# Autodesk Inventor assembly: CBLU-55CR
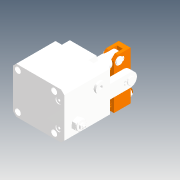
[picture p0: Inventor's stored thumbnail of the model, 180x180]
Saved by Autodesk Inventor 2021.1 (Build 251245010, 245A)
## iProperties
Created: 2019-05
Part Number: CBLU-55CR
Description: STEP AP214
Document SubType Name: Assembly
Designer: user
Title: CBLU-55CR.STEP
Revision Number: ÈÎºÎ
Sending System: SolidWorks 2016
Preprocessor: SwSTEP 2.0
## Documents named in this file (15)
- D:\Vault_2016\Projekty\Clamptek\Hydraulic\CBLU\CBLU-55\Inventor\CBLU-55CR\CBLU-55CR.iam
- D:\Vault_2016\Projekty\Clamptek\Hydraulic\CBLU\CBLU-55\Inventor\CBLU-55CR\CBLU-55CR±¾Ìå_2_1.ipt
- D:\Vault_2016\Projekty\Clamptek\Hydraulic\CBLU\CBLU-55\Inventor\CBLU-55CR\changxiao.ipt
- D:\Vault_2016\Projekty\Clamptek\Hydraulic\CBLU\CBLU-55\Inventor\CBLU-55CR\duanxiao.ipt
- D:\Vault_2016\Projekty\Clamptek\Hydraulic\CBLU\CBLU-55\Inventor\CBLU-55CR\huosaigan_5.ipt
- D:\Vault_2016\Projekty\Clamptek\Hydraulic\CBLU\CBLU-55\Inventor\CBLU-55CR\kahuang.ipt
- D:\Vault_2016\Projekty\Clamptek\Hydraulic\CBLU\CBLU-55\Inventor\CBLU-55CR\kahuang01.ipt
- D:\Vault_2016\Projekty\Clamptek\Hydraulic\CBLU\CBLU-55\Inventor\CBLU-55CR\liangan.ipt
- D:\Vault_2016\Projekty\Clamptek\Hydraulic\CBLU\CBLU-55\Inventor\CBLU-55CR\luogan.ipt
- D:\Vault_2016\Projekty\Clamptek\Hydraulic\CBLU\CBLU-55\Inventor\CBLU-55CR\luomu.ipt
- D:\Vault_2016\Projekty\Clamptek\Hydraulic\CBLU\CBLU-55\Inventor\CBLU-55CR\yabi.ipt
- D:\Vault_2016\Projekty\Clamptek\Hydraulic\CBLU\CBLU-55\Inventor\CBLU-55CR\20·§Ìå.ipt
- D:\Vault_2016\Projekty\Clamptek\Hydraulic\CBLU\CBLU-55\Inventor\CBLU-55CR\20µ÷ËÙ¸Ë.ipt
- D:\Vault_2016\Projekty\Clamptek\Hydraulic\CBLU\CBLU-55\Inventor\CBLU-55CR\hex thin nuts-grades ab-chamfered gb(GB_FASTENER_NUT_STNAB M6-S).ipt
- D:\Vault_2016\Projekty\Clamptek\Hydraulic\CBLU\CBLU-55\Inventor\CBLU-55CR\ÄÚÁù½Ç¶ÂÍ·×îÐÂ1-4_1.ipt
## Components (20 placed, 20 different names)
1. CBLU-55CR±¾Ìå_2_1_1
2. changxiao_2
3. duanxiao_3
4. huosaigan_5_4
5. kahuang_5
6. kahuang01_6
7. liangan_7
8. luogan_8
9. luomu_9
10. yabi_10
11. liangan_11
12. changxiao_12
13. kahuang_13
14. kahuang01_14
15. kahuang_15
16. kahuang_16
17. 20·§Ìå_17
18. 20µ÷ËÙ¸Ë_18
19. hex thin nuts-grades ab-chamfered gb(GB_FASTENER_NUT_STNAB M6-S)_19
20. ÄÚÁù½Ç¶ÂÍ·×îÐÂ1-4_1_20
